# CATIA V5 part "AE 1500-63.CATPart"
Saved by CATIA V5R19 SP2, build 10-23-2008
Part number: AE 1500-63
Bounding box of the stored display mesh (mm): x -37.351 to 37.351, y -37.351 to 37.351, z 0 to 187
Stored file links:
  C:\Users\Bora\Desktop\3D Katı model\AE serisi\AE 1500\AE 1500-63.CATPart
  C:\Program Files\Dassault Systemes\B19\intel_a\reffiles\standard\MetricThickPitch.txt
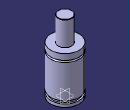
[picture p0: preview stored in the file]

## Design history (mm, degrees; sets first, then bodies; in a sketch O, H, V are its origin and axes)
Body1 (main body)
  Sketch1 on yz-plane, origin (0, 0, 0), H (0, 1, 0), V (0, 0, 1)
    point P1 (37.5, 107.5)
    point P5 (18, 186)
    point P7 (18, 186)
    point P12 (37.5, 102.5)
    point P13 (37.5, 107.5)
    point P14 (37.5, 102.5)
    line L1 (37.5, 107.5) -> (37.5, 123)
    line L2 (37.5, 0) -> (37.5, 8)
    arc A1 centre (17, 186) radius 1 from (18, 186) to (17, 187) ccw
    line L3 (18, 186) -> (18, 123)
    line L4 (33.5, 15) -> (33.5, 8)
    line L5 (37.5, 15) -> (37.5, 102.5)
    arc A2 centre (37.5, 105) radius 2.5 from (37.5, 107.5) to (37.5, 102.5) ccw
    line L6 (17, 187) -> (0, 187)
    point P15 (0, 187)
    line L7 (18, 123) -> (37.5, 123)
    line L8 (0, 0) -> (37.5, 0)
    line L9 (33.5, 15) -> (37.5, 15)
    line L10 (33.5, 8) -> (37.5, 8)
    coincidence: P15 V, P1 P13, P5 P7, P12 P14
    tangency: L6 A1
    horizontal: L7 H, L8 H, L9 H, L10 H
  Shaft1: profile Sketch1, axis Sketch1.V, angle 360
  Sketch2 on face of Shaft1 from Sketch1.L8, origin (0, 0, 0), H (1, 0, 0), V (0, -1, 0)
    point P1 (20, 0)
    distance P1 V = 20
  Hole1: placed by Sketch2, at (20, 0, 0) direction (0, 0, 1), diameter 6.647, depth 13, threaded "M8", thread diameter 8, thread depth 13, pitch 1.25
  CircPattern1: of Hole1, instances 4, angular step 90, axis from xy-plane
